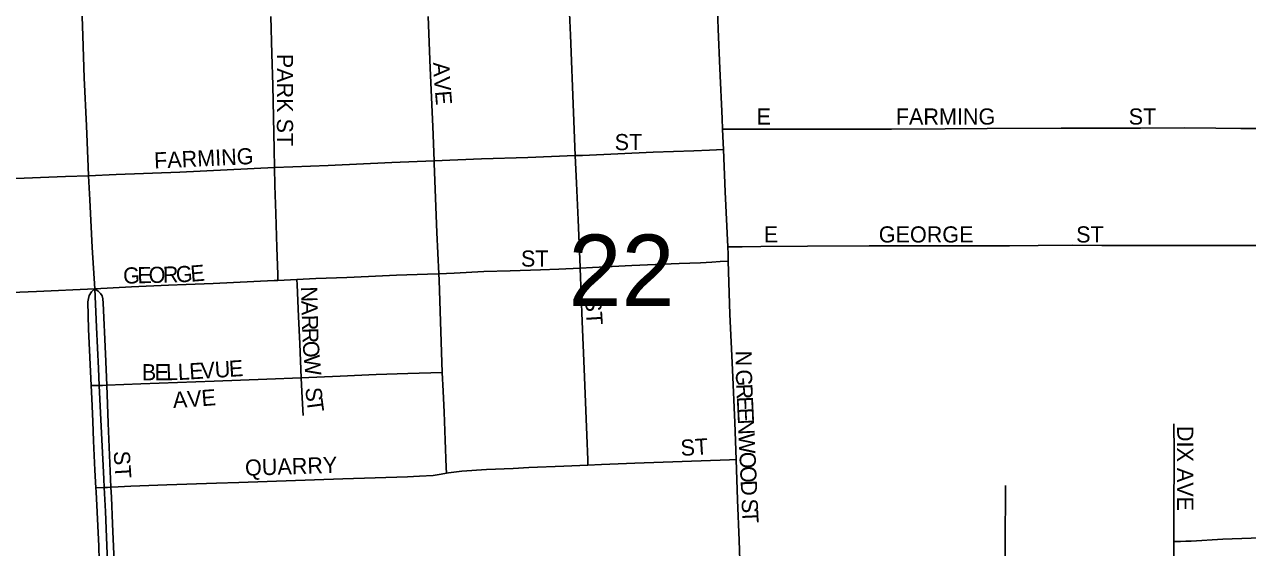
# Model space of a CAD drawing. Extents: x -9.1 to 34, y -3.1 to 22.
# Drawn here: x 5.381 to 6.099, y 20.093 to 20.4 of the extents above; entities that cross this region are included whole.
import ezdxf

# ---------------------------------------------------------------- set-up
doc = ezdxf.new("R2010")
doc.units = 0
for name, color, linetype in [('GM_X_City_Street', 7, 'Continuous'), ('GM_X_City_Street_Text', 7, 'Continuous'), ('GM_X_Section_Text', 7, 'Continuous'), ('GM_X_State_Route', 7, 'Continuous')]:
    doc.layers.add(name, color=color, linetype=linetype)

msp = doc.modelspace()

# ---------------------------------------------------------------- linework, layer by layer
at = {"layer": 'GM_X_City_Street'}
for points in [[(5.7908, 20.33829), (5.79053, 20.34463), (5.78927, 20.37389), (5.78828, 20.39705), (5.78779, 20.40874)], [(5.5279, 20.31583), (5.52764, 20.32641), (5.5269, 20.36416), (5.52639, 20.38256), (5.52574, 20.40439)], [(5.62149, 20.31972), (5.62087, 20.33986), (5.61929, 20.37419), (5.61799, 20.40438)], [(5.70439, 20.32282), (5.70337, 20.34816), (5.70151, 20.39341), (5.70101, 20.40644)], [(5.7908, 20.33829), (5.79738, 20.33829), (5.81437, 20.3383), (5.84309, 20.3383), (5.86881, 20.3383), (5.8899, 20.33831), (5.92147, 20.33849), (5.94611, 20.33868), (5.98956, 20.33886), (6.01761, 20.33886), (6.03613, 20.33886), (6.06195, 20.33904), (6.08031, 20.33887), (6.09509, 20.3387), (6.11242, 20.33871), (6.16204, 20.33855), (6.17563, 20.33855), (6.17977, 20.33855)], [(5.79132, 20.3265), (5.79115, 20.33019), (5.7908, 20.33829)], [(5.70439, 20.32282), (5.67657, 20.32178), (5.64929, 20.32087), (5.62149, 20.31972)], [(5.79132, 20.3265), (5.78322, 20.32612), (5.77391, 20.3257), (5.75014, 20.32486), (5.70872, 20.32299), (5.70439, 20.32282)], [(5.70722, 20.25687), (5.70719, 20.25739), (5.70601, 20.28513), (5.70508, 20.30673), (5.70439, 20.32282)], [(5.79384, 20.26928), (5.79242, 20.30155), (5.79132, 20.3265)], [(5.5279, 20.31583), (5.47233, 20.31318), (5.435, 20.31173), (5.41873, 20.31105)], [(5.62149, 20.31972), (5.59673, 20.31882), (5.55941, 20.31711), (5.53859, 20.31631), (5.5279, 20.31583)], [(5.52987, 20.24962), (5.52976, 20.25314), (5.52928, 20.26892), (5.52867, 20.28879), (5.52817, 20.30536), (5.5279, 20.31583)], [(5.6243, 20.25357), (5.62313, 20.27764), (5.62154, 20.31815), (5.62149, 20.31972)], [(5.41873, 20.31105), (5.4052, 20.3105), (5.37122, 20.30913), (5.35541, 20.30845), (5.3479, 20.30813), (5.33887, 20.30775)], [(5.79384, 20.26928), (5.8023, 20.26936), (5.8132, 20.26947), (5.84073, 20.26965), (5.8768, 20.2699), (5.90938, 20.26984), (5.93164, 20.26984), (5.95917, 20.26985), (5.97615, 20.27011), (5.99621, 20.2702), (6.01343, 20.27006), (6.03546, 20.27004), (6.05603, 20.27005), (6.08483, 20.27013), (6.14681, 20.2701), (6.17985, 20.27023)], [(5.79416, 20.26096), (5.79403, 20.26498), (5.79384, 20.26928)], [(5.6243, 20.25357), (5.63326, 20.25396), (5.65082, 20.25478), (5.66628, 20.25532), (5.68406, 20.25585), (5.69477, 20.25619), (5.70722, 20.25687)], [(5.70722, 20.25687), (5.71448, 20.25721), (5.73753, 20.25835), (5.76543, 20.25959), (5.77783, 20.26), (5.78449, 20.26029), (5.78941, 20.26063), (5.79416, 20.26096)], [(5.71181, 20.14125), (5.7117, 20.14426), (5.71117, 20.15886), (5.71077, 20.16834), (5.70958, 20.19781), (5.70847, 20.22556), (5.70722, 20.25687)], [(5.79883, 20.14454), (5.79807, 20.16619), (5.79662, 20.1971), (5.79516, 20.22986), (5.79416, 20.26096)], [(5.4224, 20.24474), (5.44391, 20.24582), (5.46561, 20.24675), (5.47608, 20.24713), (5.49188, 20.24781), (5.52759, 20.24947), (5.52987, 20.24962)], [(5.52987, 20.24962), (5.54101, 20.25017)], [(5.54101, 20.25017), (5.55219, 20.25076), (5.57038, 20.2514), (5.58311, 20.25185), (5.59944, 20.2526), (5.61762, 20.25328), (5.6243, 20.25357)], [(5.54346, 20.19255), (5.54269, 20.21239), (5.54205, 20.22854), (5.54116, 20.24699), (5.54101, 20.25017)], [(5.62625, 20.19567), (5.62527, 20.22543), (5.62445, 20.24975), (5.6243, 20.25357)], [(5.34174, 20.24123), (5.34778, 20.24148), (5.36868, 20.24234), (5.38812, 20.24302), (5.4224, 20.24474)], [(5.42034, 20.18791), (5.41879, 20.22093), (5.41832, 20.2371), (5.41864, 20.23906), (5.4191, 20.24072), (5.42045, 20.24285), (5.4224, 20.24474)], [(5.42949, 20.18809), (5.42868, 20.20645), (5.42738, 20.23634), (5.42711, 20.23884), (5.42665, 20.24051), (5.42575, 20.24202), (5.42438, 20.24323), (5.4224, 20.24474)], [(5.42949, 20.18809), (5.44936, 20.18891), (5.47091, 20.18967), (5.49249, 20.19055), (5.52346, 20.19177), (5.54346, 20.19255)], [(5.54346, 20.19255), (5.56634, 20.19348), (5.58753, 20.19441), (5.6062, 20.19506), (5.62625, 20.19567)], [(5.54474, 20.17029), (5.54434, 20.17726), (5.54394, 20.18437), (5.54346, 20.19255)], [(5.62882, 20.13656), (5.62868, 20.13978), (5.62803, 20.15595), (5.62736, 20.17229), (5.62683, 20.18471), (5.62625, 20.19567)], [(5.42034, 20.18791), (5.42134, 20.18793), (5.42508, 20.18801), (5.42702, 20.18806), (5.42949, 20.18809)], [(5.42304, 20.12789), (5.4224, 20.13833), (5.42173, 20.15555), (5.42121, 20.16681), (5.42069, 20.18037), (5.42034, 20.18791)], [(5.43192, 20.12827), (5.43036, 20.16587), (5.42949, 20.18809)], [(6.05562, 20.09643), (6.05562, 20.09861), (6.05566, 20.11012), (6.0557, 20.12196), (6.0558, 20.13808), (6.05587, 20.14893), (6.05565, 20.16554)], [(5.62882, 20.13656), (5.63004, 20.13681), (5.63777, 20.13769), (5.65232, 20.13859), (5.66787, 20.13921), (5.6772, 20.13985), (5.69768, 20.14069), (5.71181, 20.14125)], [(5.71181, 20.14125), (5.71981, 20.14157), (5.7394, 20.14247), (5.79483, 20.1444), (5.79883, 20.14454)], [(5.80167, 20.06693), (5.80138, 20.07371), (5.80053, 20.09698), (5.79966, 20.1208), (5.79883, 20.14454)], [(5.43192, 20.12827), (5.43608, 20.1285), (5.44364, 20.12885), (5.46472, 20.12974), (5.49375, 20.13065), (5.50689, 20.13115), (5.56803, 20.13328), (5.60595, 20.13448), (5.613, 20.13469), (5.62108, 20.13522), (5.62565, 20.13592), (5.62882, 20.13656)], [(5.42304, 20.12789), (5.42794, 20.12812), (5.42981, 20.12821), (5.43192, 20.12827)], [(5.42584, 20.06509), (5.42555, 20.0739), (5.42496, 20.08549), (5.42476, 20.09374), (5.42319, 20.12556), (5.42304, 20.12789)], [(5.43459, 20.06532), (5.43418, 20.07567), (5.43282, 20.10684), (5.43213, 20.12246), (5.43192, 20.12827)], [(5.95651, 20.0731), (5.95656, 20.08276), (5.95661, 20.08902), (5.95669, 20.09997), (5.95674, 20.10718), (5.95681, 20.11588), (5.9569, 20.12932)], [(6.05562, 20.09643), (6.0596, 20.0965), (6.06269, 20.09655), (6.06579, 20.09668), (6.08435, 20.09775), (6.11227, 20.09887), (6.12754, 20.09957)], [(6.05562, 20.07709), (6.05559, 20.0894), (6.05562, 20.09643)]]:
    msp.add_lwpolyline(points, dxfattribs=at)
at = {"layer": 'GM_X_State_Route'}
for points in [[(5.42203, 20.25076), (5.42091, 20.26895), (5.41942, 20.29693), (5.41873, 20.31105), (5.41849, 20.31629), (5.41746, 20.34028), (5.41624, 20.36841), (5.41546, 20.39316), (5.41499, 20.40452), (5.41404, 20.42753), (5.41263, 20.46423), (5.41238, 20.471), (5.41109, 20.50504), (5.40943, 20.5372), (5.40808, 20.56667), (5.40663, 20.59827), (5.40616, 20.60942), (5.40556, 20.62026), (5.40491, 20.63224), (5.40449, 20.64596)], [(5.42584, 20.17195), (5.42508, 20.18801), (5.4246, 20.19802), (5.42337, 20.22227), (5.4224, 20.24474), (5.42203, 20.25076)], [(5.43279, 20.01338), (5.43145, 20.04569), (5.43065, 20.06433), (5.43062, 20.06522), (5.43005, 20.07963), (5.42927, 20.09905), (5.42867, 20.11406), (5.42794, 20.12812), (5.42768, 20.13329), (5.42622, 20.16397), (5.42584, 20.17195)]]:
    msp.add_lwpolyline(points, dxfattribs=at)

# ---------------------------------------------------------------- texts
at = {"layer": 'GM_X_City_Street_Text'}
for s, rotation, p in [('PARK ST', 270, (5.52929, 20.38259)), ('A', 272.97374, (5.62096, 20.37746)), ('V', 274.48585, (5.62141, 20.36886)), ('E', 274.59393, (5.62206, 20.36054)), ('E', 0.00001, (5.81084, 20.34103)), ('FARMING', 0.00001, (5.89251, 20.34104)), ('ST', 0.00001, (6.02918, 20.34104)), ('ST', 0.00001, (5.72751, 20.32603)), ('FARMING', 2.68234, (5.45743, 20.3152)), ('E', 0.00001, (5.81501, 20.27187)), ('GEORGE', 0.00001, (5.88251, 20.27187)), ('ST', 0.00001, (5.99834, 20.27187)), ('ST', 0.00001, (5.67251, 20.2577)), ('G', 1.33324, (5.43914, 20.2477)), ('E', 1.31126, (5.44747, 20.2479)), ('O', 1.33376, (5.45414, 20.24805)), ('R', 1.31133, (5.46247, 20.24824)), ('G', 2.54096, (5.47019, 20.24842)), ('E', 4.59392, (5.47888, 20.24881)), ('N', 271.46432, (5.54346, 20.24597)), ('A', 271.46432, (5.54367, 20.23763)), ('ST', 273.57379, (5.71012, 20.23937)), ('R', 271.45699, (5.54389, 20.2293)), ('R', 271.78683, (5.54408, 20.22174)), ('O', 274.22479, (5.54434, 20.21381)), ('W', 275.16483, (5.54496, 20.20533)), ('N', 270.10931, (5.79846, 20.20841)), ('B', 0.04858, (5.45001, 20.19104)), ('E', 0.05465, (5.45751, 20.19104)), ('L', 0.75666, (5.4643, 20.19105)), ('L', 3.05321, (5.47138, 20.19115)), ('E', 3.64897, (5.47814, 20.19151)), ('V', 3.65269, (5.48479, 20.19193)), ('U', 3.64292, (5.49311, 20.19246)), ('E', 3.63598, (5.50142, 20.193)), ('G', 272.10062, (5.79852, 20.19723)), ('A', 3.03921, (5.46848, 20.17475)), ('V', 4.24718, (5.47702, 20.1752)), ('E', 4.38111, (5.48535, 20.17582)), ('S', 275.28102, (5.54597, 20.18652)), ('R', 272.60606, (5.79883, 20.18881)), ('T', 277.44886, (5.54663, 20.1795)), ('E', 272.65352, (5.79917, 20.18131)), ('E', 272.62366, (5.79948, 20.17465)), ('N', 272.63077, (5.79978, 20.16799)), ('DIX AVE', 270, (6.05762, 20.16426)), ('ST', 3.57463, (5.76648, 20.14661)), ('W', 272.62395, (5.80016, 20.15966)), ('ST', 273.57465, (5.43345, 20.14936)), ('O', 272.63077, (5.80066, 20.14884)), ('QUARRY', 1.94418, (5.51074, 20.13495)), ('O', 272.62341, (5.80104, 20.14051)), ('D', 272.63077, (5.80142, 20.13219)), ('S', 272.65095, (5.80192, 20.12136)), ('T', 272.62366, (5.80223, 20.1147))]:
    msp.add_text(s, height=0.00947, rotation=rotation, dxfattribs=at).set_placement(p)
at = {"layer": 'GM_X_Section_Text'}
msp.add_text('22', height=0.041856, rotation=0.00001, dxfattribs=at).set_placement((5.70043, 20.23463))

doc.saveas('drawing.dxf')
